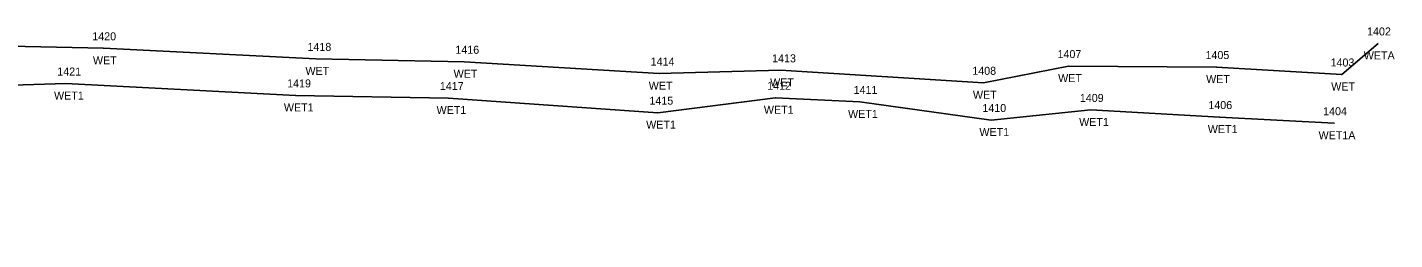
# Model space of a CAD drawing. Extents: x 1967699 to 1968370, y 1117733 to 1117905.
# Drawn here: x 1968198.7 to 1968369.6, y 1117877.9 to 1117904.4 of the extents above; entities that cross this region are included whole.
import ezdxf

# ---------------------------------------------------------------- set-up
doc = ezdxf.new("R2010")
doc.units = 0
for name, color, linetype in [('RD_EX_H2O_WetLd', 7, 'Continuous'), ('RD_EX_H2O_WetLd_txCode', 7, 'Continuous'), ('RD_SMD_Locator', 7, 'Continuous')]:
    doc.layers.add(name, color=color, linetype=linetype)

msp = doc.modelspace()

# ---------------------------------------------------------------- linework, layer by layer
at = {"layer": 'RD_EX_H2O_WetLd'}
for points in [[(1968367.53, 1117902.43), (1968362.98, 1117898.55), (1968347.35, 1117899.48), (1968328.86, 1117899.6), (1968318.21, 1117897.51), (1968292.87, 1117899.07), (1968277.7, 1117898.66), (1968253.32, 1117900.14), (1968234.81, 1117900.5), (1968208.25, 1117901.82), (1968190.62, 1117902.21), (1968163.17, 1117903.04), (1968147.64, 1117899.29), (1968127.85, 1117903.36), (1968087.96, 1117902.71), (1968056.92, 1117899.97), (1968032.7, 1117893.9)], [(1968362.05, 1117892.46), (1968347.73, 1117893.23), (1968331.65, 1117894.12), (1968319.19, 1117892.86), (1968302.77, 1117895.12), (1968292.25, 1117895.64), (1968277.54, 1117893.78), (1968251.35, 1117895.61), (1968232.27, 1117895.94), (1968203.56, 1117897.42), (1968184.88, 1117896.85), (1968165.45, 1117895.9), (1968147.25, 1117896.52), (1968127.56, 1117896.46), (1968096.98, 1117896.55), (1968076.04, 1117897.19), (1968057.43, 1117895.18), (1968037.49, 1117884.16), (1968020.4, 1117877.91)]]:
    msp.add_lwpolyline(points, dxfattribs=at)
at = {"layer": 'RD_SMD_Locator'}
for centre in [(1968208.25, 1117901.82), (1968367.53, 1117902.43), (1968234.81, 1117900.5), (1968253.32, 1117900.14), (1968328.86, 1117899.6), (1968347.35, 1117899.48), (1968277.7, 1117898.66), (1968292.87, 1117899.07), (1968318.21, 1117897.51), (1968362.98, 1117898.55), (1968203.56, 1117897.42), (1968232.27, 1117895.94), (1968251.35, 1117895.61), (1968292.25, 1117895.64), (1968302.77, 1117895.12), (1968331.65, 1117894.12), (1968277.54, 1117893.78), (1968319.19, 1117892.86), (1968347.73, 1117893.23), (1968362.05, 1117892.46)]:
    msp.add_circle(centre, 0.001, dxfattribs=at)

# ---------------------------------------------------------------- texts
at = {"layer": 'RD_EX_H2O_WetLd_txCode'}
for s, p in [('1402', (1968366.15, 1117903.43)), ('1420', (1968206.86, 1117902.82)), ('1418', (1968233.75, 1117901.5)), ('1416', (1968252.23, 1117901.14)), ('1413', (1968291.81, 1117900.07)), ('1407', (1968327.47, 1117900.6)), ('1405', (1968345.96, 1117900.48)), ('WETA', (1968365.74, 1117900.43)), ('1421', (1968202.49, 1117898.42)), ('WET', (1968206.94, 1117899.82)), ('WET', (1968233.5, 1117898.5)), ('1414', (1968276.63, 1117899.66)), ('1408', (1968316.82, 1117898.51)), ('1403', (1968361.59, 1117899.55)), ('1419', (1968231.21, 1117896.94)), ('1417', (1968250.29, 1117896.61)), ('WET', (1968252.01, 1117898.14)), ('WET', (1968276.39, 1117896.66)), ('1412', (1968291.19, 1117896.64)), ('WET', (1968291.56, 1117897.07)), ('WET', (1968327.55, 1117897.6)), ('WET', (1968346.04, 1117897.48)), ('WET', (1968361.67, 1117896.55)), ('WET1', (1968202.08, 1117895.42)), ('1411', (1968301.99, 1117896.12)), ('WET', (1968316.9, 1117895.51)), ('1409', (1968330.26, 1117895.12)), ('WET1', (1968230.8, 1117893.94)), ('WET1', (1968249.88, 1117893.61)), ('1415', (1968276.48, 1117894.78)), ('WET1', (1968290.78, 1117893.64)), ('WET1', (1968301.3, 1117893.12)), ('1410', (1968318.08, 1117893.86)), ('1406', (1968346.32, 1117894.23)), ('1404', (1968360.66, 1117893.46)), ('WET1', (1968276.07, 1117891.78)), ('WET1', (1968330.17, 1117892.12)), ('WET1', (1968317.71, 1117890.86)), ('WET1', (1968346.25, 1117891.23)), ('WET1A', (1968360.09, 1117890.46))]:
    msp.add_text(s, height=1, dxfattribs=at).set_placement(p)

doc.saveas('drawing.dxf')
